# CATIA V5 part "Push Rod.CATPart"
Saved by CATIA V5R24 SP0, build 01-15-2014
Part number: Push Rod
Bounding box of the stored display mesh (mm): x -22.994 to 22.994, y 0 to 164.429, z -22.994 to 22.994
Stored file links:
  E:\Desktop_RNH\학부 CAD 수업 자료\[CAD_V2]강의자료(CAD)_2017년 이후\툴바예제\DMU Kinematics_2017\Example\Push Rod.CATPart

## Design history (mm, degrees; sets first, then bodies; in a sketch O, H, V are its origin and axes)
Body1 (main body)
  Sketch1 on xy-plane, origin (0, 0, 0), H (1, 0, 0), V (0, 1, 0)
    line L1 (0, 2.5) -> (0, 0)
    line L2 (0, 2.5) -> (0, 70)
    line L3 (0, 164.4288) -> (0, 70)
    line L4 (6, 6) -> (6, 150)
    arc A1 centre (0, 6) radius 6 from (0, 0) to (6, 6) ccw
    point P4 (0, 6)
    point P5 (6, 6)
    point P6 (6, 6)
    point P7 (6, 6)
    arc A2 centre (11, 150) radius 5 from (8.871, 154.5241) to (6, 150) ccw
    line L5 (8.871, 154.5241) -> (23, 161.173)
    line L6 (23, 161.173) -> (23, 163.173)
    arc A3 centre (0, -46.827) radius 211.2558 from (23, 163.173) to (0, 164.4288) ccw
    vertical: L4 V
    coincidence: P4 L2, A1 P5, P5 L4, A1 P6, L4 P7
    tangency: A1 L4
  Shaft1: profile Sketch1, axis Sketch1.L1, angle 360
  Point1: (0, 0, 0)
  Plane1: type Offset, RefPlane zx-plane, Offset 220
  Sketch2 on Plane1, origin (0, 220, 0), H (-1, 0, 0), V (0, 0, 1)
    point P1 (-39, 0)
    line L1 (-39, 0) -> (33, 0)
    coincidence: P1 H
    horizontal: L1 H
  Project1: ToProject Sketch2, Support Shaft1
  Sketch3 on xy-plane, origin (0, 0, 0), H (1, 0, 0), V (0, 1, 0)
    point P1 (0, 164.4288)
  Plane2: type Tangent, Support face of Shaft1 from Sketch1.A3, RefPoint Sketch3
